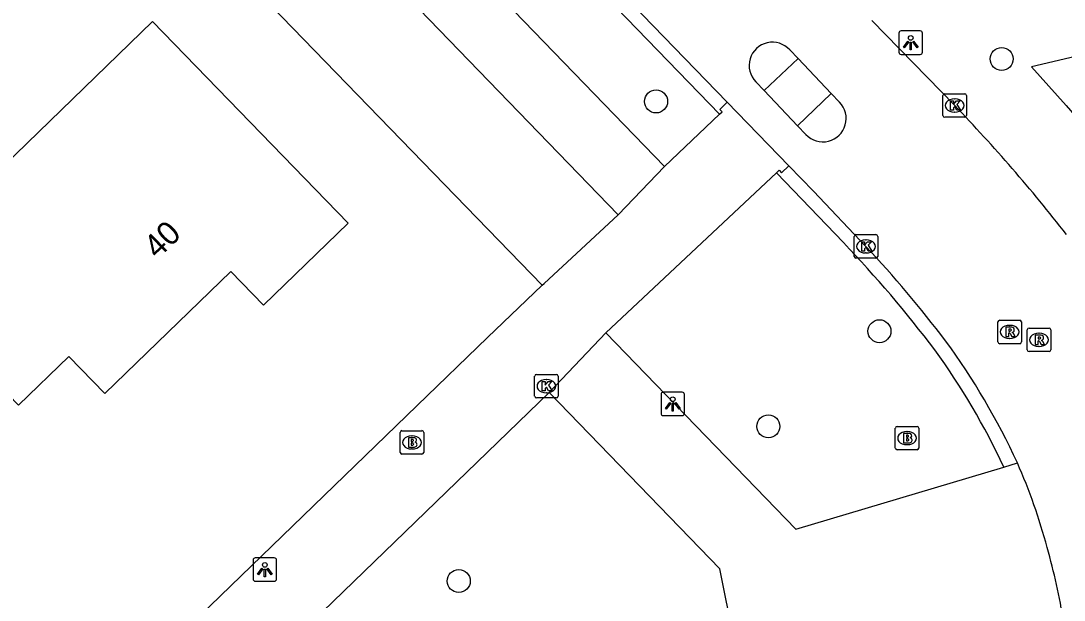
# Model space of a CAD drawing. Extents: x 157663 to 158496, y 379212 to 380934.
# Drawn here: x 158083.8 to 158128.21, y 380348.23 to 380372.89 of the extents above; entities that cross this region are included whole.
import ezdxf

# ---------------------------------------------------------------- set-up
doc = ezdxf.new("R2010")
doc.units = 0
for name, color, linetype in [('IMGEO_Boom', 7, 'Continuous'), ('IMGEO_Brandkraan', 7, 'Continuous'), ('IMGEO_Groenvoorziening', 7, 'Continuous'), ('IMGEO_Kolk', 7, 'Continuous'), ('IMGEO_Lichtpunt', 7, 'Continuous'), ('IMGEO_Pand', 7, 'Continuous'), ('IMGEO_Pand_nummerreeks', 7, 'Continuous'), ('IMGEO_Rijbaan_lokaal_open', 7, 'Continuous'), ('IMGEO_Rioolput', 7, 'Continuous'), ('IMGEO_Voetpad_open', 7, 'Continuous')]:
    doc.layers.add(name, color=color, linetype=linetype)

msp = doc.modelspace()

# ---------------------------------------------------------------- linework, layer by layer
at = {"layer": 'IMGEO_Boom'}
for centre in [(158125.552, 380371.264), (158110.84, 380369.456), (158120.35, 380359.676), (158115.62, 380355.624), (158102.44, 380349.041)]:
    msp.add_circle(centre, 0.489, dxfattribs=at)
at = {"layer": 'IMGEO_Brandkraan'}
for p, q in [((158121.025, 380354.7), (158121.025, 380355.552)), ((158121.1, 380355.626), (158121.952, 380355.626)), ((158122.026, 380355.552), (158122.026, 380354.7)), ((158099.945, 380354.516), (158099.945, 380355.368)), ((158100.02, 380355.442), (158100.872, 380355.442)), ((158100.433, 380355.222), (158100.458, 380355.222)), ((158100.946, 380355.368), (158100.946, 380354.516)), ((158121.513, 380355.406), (158121.538, 380355.406)), ((158100.456, 380354.662), (158100.431, 380354.662)), ((158121.952, 380354.626), (158121.1, 380354.626)), ((158121.536, 380354.846), (158121.511, 380354.846)), ((158100.872, 380354.442), (158100.02, 380354.442))]:
    msp.add_line(p, q, dxfattribs=at)
for points in [[(158121.025, 380354.7), (158121.025, 380355.552)], [(158121.1, 380355.626), (158121.952, 380355.626)], [(158122.026, 380355.552), (158122.026, 380354.7)], [(158099.945, 380354.516), (158099.945, 380355.368)], [(158100.02, 380355.442), (158100.872, 380355.442)], [(158100.293, 380355.142), (158100.293, 380354.742), (158100.506, 380354.742)], [(158100.524, 380355.142), (158100.293, 380355.142)], [(158100.472, 380355.061), (158100.418, 380355.061), (158100.418, 380354.985)], [(158100.946, 380355.368), (158100.946, 380354.516)], [(158121.373, 380355.326), (158121.373, 380354.926), (158121.586, 380354.926)], [(158121.604, 380355.326), (158121.373, 380355.326)], [(158121.552, 380355.245), (158121.498, 380355.245), (158121.498, 380355.169)], [(158121.498, 380355.169), (158121.551, 380355.169)], [(158121.56, 380355.093), (158121.498, 380355.093), (158121.498, 380355.012)], [(158100.418, 380354.985), (158100.471, 380354.985)], [(158100.48, 380354.909), (158100.418, 380354.909), (158100.418, 380354.828)], [(158100.418, 380354.828), (158100.48, 380354.828)], [(158121.952, 380354.626), (158121.1, 380354.626)], [(158121.498, 380355.012), (158121.56, 380355.012)], [(158100.872, 380354.442), (158100.02, 380354.442)]]:
    msp.add_lwpolyline(points, dxfattribs=at)
for centre, radius, start, end in [((158121.102, 380355.55), 0.0765, 91.552, 178.448), ((158121.102, 380355.55), 0.0765, 91.552, 178.448), ((158121.95, 380355.55), 0.0765, 1.552, 88.448), ((158121.95, 380355.55), 0.0765, 1.552, 88.448), ((158100.022, 380355.366), 0.0765, 91.552, 178.448), ((158100.022, 380355.366), 0.0765, 91.552, 178.448), ((158100.473, 380355.023), 0.0379, 267.8285, 90.9355), ((158100.528, 380354.997), 0.145, 59.4692, 91.5367), ((158100.553, 380355.044), 0.0922, 285.5137, 58.1501), ((158100.87, 380355.366), 0.0765, 1.552, 88.448), ((158100.87, 380355.366), 0.0765, 1.552, 88.448), ((158121.553, 380355.207), 0.0379, 267.8285, 90.9355), ((158121.561, 380355.052), 0.0404, 269.8759, 90.5077), ((158121.608, 380355.181), 0.145, 59.4692, 91.5367), ((158121.633, 380355.228), 0.0922, 285.5137, 58.1501), ((158121.638, 380355.036), 0.105, 301.3115, 78.989), ((158100.481, 380354.868), 0.0404, 269.8759, 90.5077), ((158100.512, 380354.993), 0.251, 268.6676, 293.5347), ((158100.558, 380354.852), 0.105, 301.3115, 78.989), ((158121.102, 380354.702), 0.0765, 181.552, 268.448), ((158121.102, 380354.702), 0.0765, 181.552, 268.448), ((158121.592, 380355.177), 0.251, 268.6676, 293.5347), ((158121.95, 380354.702), 0.0765, 271.552, 358.448), ((158121.95, 380354.702), 0.0765, 271.552, 358.448), ((158100.022, 380354.518), 0.0765, 181.552, 268.448), ((158100.022, 380354.518), 0.0765, 181.552, 268.448), ((158100.87, 380354.518), 0.0765, 271.552, 358.448), ((158100.87, 380354.518), 0.0765, 271.552, 358.448)]:
    msp.add_arc(centre, radius, start, end, dxfattribs=at)
for centre, major_axis, ratio, start_param, end_param in [((158100.432, 380354.942), (-0.387, 0.002), 0.722429, 4.712389, 7.853982), ((158100.457, 380354.942), (-0.39, 0.002), 0.717154, 1.570796, 4.712389), ((158121.512, 380355.126), (-0.387, 0.002), 0.722429, 4.712389, 7.853982), ((158121.537, 380355.126), (-0.39, 0.002), 0.717154, 1.570796, 4.712389)]:
    msp.add_ellipse(centre, major_axis=major_axis, ratio=ratio, start_param=start_param, end_param=end_param, dxfattribs=at)
at = {"layer": 'IMGEO_Groenvoorziening'}
msp.add_lwpolyline([(158105.995, 380361.632), (158075.944, 380392.592), (158075.753, 380392.408), (158075.676, 380392.485), (158052.218, 380370.37), (158052.442, 380369.146), (158059.5, 380330.252), (158063.82, 380331.088)], dxfattribs=at)
at = {"layer": 'IMGEO_Kolk'}
for p, q in [((158123.052, 380368.855), (158123.052, 380369.707)), ((158123.127, 380369.781), (158123.979, 380369.781)), ((158124.053, 380369.707), (158124.053, 380368.855)), ((158123.54, 380369.561), (158123.565, 380369.561)), ((158123.563, 380369.001), (158123.538, 380369.001)), ((158123.979, 380368.781), (158123.127, 380368.781)), ((158119.273, 380362.859), (158119.273, 380363.711)), ((158119.348, 380363.785), (158120.2, 380363.785)), ((158119.761, 380363.565), (158119.786, 380363.565)), ((158120.274, 380363.711), (158120.274, 380362.859)), ((158120.2, 380362.785), (158119.348, 380362.785)), ((158119.784, 380363.005), (158119.759, 380363.005)), ((158105.671, 380356.908), (158105.671, 380357.76)), ((158105.746, 380357.834), (158106.598, 380357.834)), ((158106.672, 380357.76), (158106.672, 380356.908)), ((158106.159, 380357.614), (158106.184, 380357.614)), ((158106.598, 380356.834), (158105.746, 380356.834)), ((158106.182, 380357.054), (158106.157, 380357.054))]:
    msp.add_line(p, q, dxfattribs=at)
for points in [[(158123.052, 380368.855), (158123.052, 380369.707)], [(158123.127, 380369.781), (158123.979, 380369.781)], [(158124.053, 380369.707), (158124.053, 380368.855)], [(158123.373, 380369.481), (158123.496, 380369.481), (158123.496, 380369.33), (158123.626, 380369.481), (158123.79, 380369.481), (158123.644, 380369.33), (158123.797, 380369.081), (158123.645, 380369.081), (158123.56, 380369.245), (158123.496, 380369.178), (158123.496, 380369.081), (158123.373, 380369.081), (158123.373, 380369.481)], [(158123.979, 380368.781), (158123.127, 380368.781)], [(158119.273, 380362.859), (158119.273, 380363.711)], [(158119.348, 380363.785), (158120.2, 380363.785)], [(158119.594, 380363.485), (158119.717, 380363.485), (158119.717, 380363.334), (158119.847, 380363.485), (158120.011, 380363.485), (158119.865, 380363.334), (158120.018, 380363.085), (158119.866, 380363.085), (158119.781, 380363.249), (158119.717, 380363.182), (158119.717, 380363.085), (158119.594, 380363.085), (158119.594, 380363.485)], [(158120.274, 380363.711), (158120.274, 380362.859)], [(158120.2, 380362.785), (158119.348, 380362.785)], [(158105.671, 380356.908), (158105.671, 380357.76)], [(158105.746, 380357.834), (158106.598, 380357.834)], [(158106.672, 380357.76), (158106.672, 380356.908)], [(158105.992, 380357.534), (158106.115, 380357.534), (158106.115, 380357.383), (158106.245, 380357.534), (158106.409, 380357.534), (158106.263, 380357.383), (158106.416, 380357.134), (158106.264, 380357.134), (158106.179, 380357.298), (158106.115, 380357.231), (158106.115, 380357.134), (158105.992, 380357.134), (158105.992, 380357.534)], [(158106.598, 380356.834), (158105.746, 380356.834)]]:
    msp.add_lwpolyline(points, dxfattribs=at)
for centre, start, end in [((158123.129, 380369.705), 91.552, 178.448), ((158123.129, 380369.705), 91.552, 178.448), ((158123.977, 380369.705), 1.552, 88.448), ((158123.977, 380369.705), 1.552, 88.448), ((158123.129, 380368.857), 181.552, 268.448), ((158123.129, 380368.857), 181.552, 268.448), ((158123.977, 380368.857), 271.552, 358.448), ((158123.977, 380368.857), 271.552, 358.448), ((158119.35, 380363.709), 91.552, 178.448), ((158119.35, 380363.709), 91.552, 178.448), ((158120.198, 380363.709), 1.552, 88.448), ((158120.198, 380363.709), 1.552, 88.448), ((158119.35, 380362.861), 181.552, 268.448), ((158119.35, 380362.861), 181.552, 268.448), ((158120.198, 380362.861), 271.552, 358.448), ((158120.198, 380362.861), 271.552, 358.448), ((158105.748, 380357.758), 91.552, 178.448), ((158105.748, 380357.758), 91.552, 178.448), ((158106.596, 380357.758), 1.552, 88.448), ((158106.596, 380357.758), 1.552, 88.448), ((158105.748, 380356.91), 181.552, 268.448), ((158105.748, 380356.91), 181.552, 268.448), ((158106.596, 380356.91), 271.552, 358.448), ((158106.596, 380356.91), 271.552, 358.448)]:
    msp.add_arc(centre, 0.0765, start, end, dxfattribs=at)
for centre, major_axis, ratio, start_param, end_param in [((158123.539, 380369.281), (-0.387, 0.002), 0.722429, 4.712389, 7.853982), ((158123.564, 380369.281), (-0.39, 0.002), 0.717154, 1.570796, 4.712389), ((158119.76, 380363.285), (-0.387, 0.002), 0.722429, 4.712389, 7.853982), ((158119.785, 380363.285), (-0.39, 0.002), 0.717154, 1.570796, 4.712389), ((158106.158, 380357.334), (-0.387, 0.002), 0.722429, 4.712389, 7.853982), ((158106.183, 380357.334), (-0.39, 0.002), 0.717154, 1.570796, 4.712389)]:
    msp.add_ellipse(centre, major_axis=major_axis, ratio=ratio, start_param=start_param, end_param=end_param, dxfattribs=at)
at = {"layer": 'IMGEO_Lichtpunt'}
for p, q in [((158121.18, 380372.361), (158121.18, 380371.554)), ((158121.18, 380372.361), (158121.18, 380371.554)), ((158122.082, 380372.456), (158121.274, 380372.456)), ((158122.082, 380372.456), (158121.274, 380372.456)), ((158122.176, 380371.554), (158122.176, 380372.361)), ((158122.176, 380371.554), (158122.176, 380372.361)), ((158121.274, 380371.46), (158122.082, 380371.46)), ((158121.274, 380371.46), (158122.082, 380371.46)), ((158111.05, 380356.983), (158111.05, 380356.176)), ((158111.05, 380356.983), (158111.05, 380356.176)), ((158111.952, 380357.078), (158111.144, 380357.078)), ((158111.952, 380357.078), (158111.144, 380357.078)), ((158112.046, 380356.176), (158112.046, 380356.983)), ((158112.046, 380356.176), (158112.046, 380356.983)), ((158111.144, 380356.082), (158111.952, 380356.082)), ((158111.144, 380356.082), (158111.952, 380356.082)), ((158093.685, 380349.932), (158093.685, 380349.125)), ((158093.685, 380349.932), (158093.685, 380349.125)), ((158094.587, 380350.027), (158093.779, 380350.027)), ((158094.587, 380350.027), (158093.779, 380350.027)), ((158094.681, 380349.125), (158094.681, 380349.932)), ((158094.681, 380349.125), (158094.681, 380349.932)), ((158093.779, 380349.031), (158094.587, 380349.031)), ((158093.779, 380349.031), (158094.587, 380349.031))]:
    msp.add_line(p, q, dxfattribs=at)
for points in [[(158121.554, 380372.025), (158121.593, 380371.997), (158121.405, 380371.735), (158121.367, 380371.762), (158121.554, 380372.025)], [(158121.656, 380371.977), (158121.703, 380371.977), (158121.703, 380371.655), (158121.656, 380371.655), (158121.656, 380371.977)], [(158121.766, 380371.997), (158121.804, 380372.024), (158121.991, 380371.762), (158121.952, 380371.734), (158121.766, 380371.997)], [(158111.424, 380356.647), (158111.463, 380356.619), (158111.275, 380356.357), (158111.237, 380356.384), (158111.424, 380356.647)], [(158111.526, 380356.599), (158111.573, 380356.599), (158111.573, 380356.277), (158111.526, 380356.277), (158111.526, 380356.599)], [(158111.636, 380356.619), (158111.674, 380356.646), (158111.861, 380356.384), (158111.822, 380356.356), (158111.636, 380356.619)], [(158094.059, 380349.596), (158094.098, 380349.568), (158093.91, 380349.306), (158093.872, 380349.333), (158094.059, 380349.596)], [(158094.161, 380349.548), (158094.208, 380349.548), (158094.208, 380349.226), (158094.161, 380349.226), (158094.161, 380349.548)], [(158094.271, 380349.568), (158094.309, 380349.595), (158094.496, 380349.333), (158094.457, 380349.305), (158094.271, 380349.568)]]:
    msp.add_lwpolyline(points, dxfattribs=at)
for centre in [(158121.679, 380372.159), (158111.549, 380356.781), (158094.184, 380349.73)]:
    msp.add_circle(centre, 0.0994, dxfattribs=at)
for centre, start, end in [((158121.274, 380372.361), 90, 180), ((158121.274, 380372.361), 90, 180), ((158122.082, 380372.361), 0, 90), ((158122.082, 380372.361), 0, 90), ((158121.274, 380371.554), 180, 270), ((158121.274, 380371.554), 180, 270), ((158122.082, 380371.554), 270, 0), ((158122.082, 380371.554), 270, 360), ((158111.144, 380356.983), 90, 180), ((158111.144, 380356.983), 90, 180), ((158111.952, 380356.983), 0, 90), ((158111.952, 380356.983), 0, 90), ((158111.144, 380356.176), 180, 270), ((158111.144, 380356.176), 180, 270), ((158111.952, 380356.176), 270, 0), ((158111.952, 380356.176), 270, 360), ((158093.779, 380349.932), 90, 180), ((158093.779, 380349.932), 90, 180), ((158094.587, 380349.932), 0, 90), ((158094.587, 380349.932), 0, 90), ((158093.779, 380349.125), 180, 270), ((158093.779, 380349.125), 180, 270), ((158094.587, 380349.125), 270, 0), ((158094.587, 380349.125), 270, 360)]:
    msp.add_arc(centre, 0.0946, start, end, dxfattribs=at)
at = {"layer": 'IMGEO_Pand'}
msp.add_lwpolyline([(158087.367, 380357.019), (158085.835, 380358.598), (158083.703, 380356.53), (158076.024, 380364.445), (158075.857, 380364.617), (158078.684, 380367.359), (158081.127, 380364.84), (158089.399, 380372.864), (158097.735, 380364.271), (158094.134, 380360.778), (158092.731, 380362.224), (158087.367, 380357.019)], dxfattribs=at)
at = {"layer": 'IMGEO_Rijbaan_lokaal_open'}
for points in [[(158113.871, 380369.425), (158099.931, 380383.806)], [(158120.025, 380372.906), (158123.553, 380369.281)], [(158116.894, 380371.29), (158116.528, 380371.649)], [(158116.894, 380371.29), (158118.291, 380369.799)], [(158115.083, 380370.294), (158115.44, 380369.92)], [(158116.857, 380368.42), (158115.44, 380369.92)], [(158118.643, 380369.424), (158118.291, 380369.799)], [(158116.496, 380366.721), (158113.871, 380369.425)], [(158116.857, 380368.42), (158117.221, 380368.05)], [(158116.496, 380366.721), (158117.545, 380365.64), (158119.774, 380363.285)]]:
    msp.add_lwpolyline(points, dxfattribs=at)
for centre, radius, start, end in [((158115.792, 380370.986), 0.991, 42.0256, 224.2924), ((158117.944, 380368.725), 0.989, 223.0415, 44.9914), ((158070.396, 380318.319), 73.64, 38.13735, 43.79233), ((158083.404, 380329.178), 49.86, 37.1231, 43.1613), ((158099.018, 380341.558), 29.943, 24.7004, 36.2663), ((158104.288, 380344.344), 23.993, 14.7771, 23.9133), ((158103.173, 380343.419), 25.314, 8.7999, 16.1583)]:
    msp.add_arc(centre, radius, start, end, dxfattribs=at)
at = {"layer": 'IMGEO_Rioolput'}
for p, q in [((158125.393, 380359.219), (158125.393, 380360.071)), ((158125.468, 380360.145), (158126.32, 380360.145)), ((158125.881, 380359.925), (158125.906, 380359.925)), ((158126.394, 380360.071), (158126.394, 380359.219)), ((158126.641, 380358.882), (158126.641, 380359.734)), ((158126.716, 380359.808), (158127.568, 380359.808)), ((158127.129, 380359.588), (158127.154, 380359.588)), ((158127.642, 380359.734), (158127.642, 380358.882)), ((158126.32, 380359.145), (158125.468, 380359.145)), ((158125.904, 380359.365), (158125.879, 380359.365)), ((158127.152, 380359.028), (158127.127, 380359.028)), ((158127.568, 380358.808), (158126.716, 380358.808))]:
    msp.add_line(p, q, dxfattribs=at)
for points in [[(158125.393, 380359.219), (158125.393, 380360.071)], [(158125.468, 380360.145), (158126.32, 380360.145)], [(158126.394, 380360.071), (158126.394, 380359.219)], [(158125.982, 380359.843), (158125.73, 380359.845), (158125.73, 380359.445)], [(158125.73, 380359.445), (158125.854, 380359.445), (158125.854, 380359.607), (158125.865, 380359.607)], [(158125.908, 380359.764), (158125.854, 380359.764), (158125.854, 380359.683)], [(158125.854, 380359.683), (158125.906, 380359.683)], [(158125.912, 380359.578), (158125.983, 380359.445), (158126.123, 380359.445), (158126.058, 380359.571)], [(158126.641, 380358.882), (158126.641, 380359.734)], [(158126.716, 380359.808), (158127.568, 380359.808)], [(158127.23, 380359.506), (158126.978, 380359.508), (158126.978, 380359.108)], [(158127.642, 380359.734), (158127.642, 380358.882)], [(158126.32, 380359.145), (158125.468, 380359.145)], [(158126.978, 380359.108), (158127.102, 380359.108), (158127.102, 380359.27), (158127.113, 380359.27)], [(158127.156, 380359.427), (158127.102, 380359.427), (158127.102, 380359.346)], [(158127.102, 380359.346), (158127.154, 380359.346)], [(158127.16, 380359.241), (158127.231, 380359.108), (158127.371, 380359.108), (158127.306, 380359.234)], [(158127.568, 380358.808), (158126.716, 380358.808)]]:
    msp.add_lwpolyline(points, dxfattribs=at)
for centre, radius, start, end in [((158125.47, 380360.069), 0.0765, 91.552, 178.448), ((158125.47, 380360.069), 0.0765, 91.552, 178.448), ((158126.318, 380360.069), 0.0765, 1.552, 88.448), ((158126.318, 380360.069), 0.0765, 1.552, 88.448), ((158125.864, 380359.554), 0.0533, 26.0293, 88.6989), ((158125.89, 380359.872), 0.19, 274.7715, 282.9687), ((158125.914, 380359.668), 0.0964, 77.0061, 93.1865), ((158125.928, 380359.725), 0.0378, 276.6634, 79.6772), ((158125.981, 380359.733), 0.109, 350.3612, 89.416), ((158125.979, 380359.733), 0.112, 277.5842, 350.9817), ((158125.963, 380359.518), 0.108, 29.5134, 73.7905), ((158126.718, 380359.732), 0.0765, 91.552, 178.448), ((158126.718, 380359.732), 0.0765, 91.552, 178.448), ((158127.229, 380359.396), 0.109, 350.3612, 89.416), ((158127.566, 380359.732), 0.0765, 1.552, 88.448), ((158127.566, 380359.732), 0.0765, 1.552, 88.448), ((158125.47, 380359.221), 0.0765, 181.552, 268.448), ((158125.47, 380359.221), 0.0765, 181.552, 268.448), ((158126.318, 380359.221), 0.0765, 271.552, 358.448), ((158126.318, 380359.221), 0.0765, 271.552, 358.448), ((158127.112, 380359.217), 0.0533, 26.0293, 88.6989), ((158127.138, 380359.535), 0.19, 274.7715, 282.9687), ((158127.162, 380359.331), 0.0964, 77.0061, 93.1865), ((158127.176, 380359.388), 0.0378, 276.6634, 79.6772), ((158127.227, 380359.396), 0.112, 277.5842, 350.9817), ((158127.211, 380359.181), 0.108, 29.5134, 73.7905), ((158126.718, 380358.884), 0.0765, 181.552, 268.448), ((158126.718, 380358.884), 0.0765, 181.552, 268.448), ((158127.566, 380358.884), 0.0765, 271.552, 358.448), ((158127.566, 380358.884), 0.0765, 271.552, 358.448)]:
    msp.add_arc(centre, radius, start, end, dxfattribs=at)
for centre, major_axis, ratio, start_param, end_param in [((158125.88, 380359.645), (-0.387, 0.002), 0.722429, 4.712389, 7.853982), ((158125.905, 380359.645), (-0.39, 0.002), 0.717154, 1.570796, 4.712389), ((158127.128, 380359.308), (-0.387, 0.002), 0.722429, 4.712389, 7.853982), ((158127.153, 380359.308), (-0.39, 0.002), 0.717154, 1.570796, 4.712389)]:
    msp.add_ellipse(centre, major_axis=major_axis, ratio=ratio, start_param=start_param, end_param=end_param, dxfattribs=at)
at = {"layer": 'IMGEO_Voetpad_open'}
for points in [[(158111.192, 380366.685), (158093.226, 380385.279), (158095.545, 380387.499), (158113.544, 380368.914)], [(158109.224, 380364.626), (158090.592, 380383.892), (158090.472, 380384.897)], [(158143.242, 380374.803), (158126.816, 380370.925), (158127.564, 380370.111), (158128.3, 380369.287), (158129.024, 380368.452), (158129.736, 380367.607), (158130.436, 380366.751), (158131.123, 380365.886), (158133.759, 380362.09), (158145.562, 380364.862)], [(158115.44, 380369.92), (158116.894, 380371.29)], [(158118.291, 380369.799), (158116.857, 380368.42)], [(158113.544, 380368.914), (158113.647, 380369.012), (158113.548, 380369.117), (158113.871, 380369.425)], [(158113.544, 380368.914), (158111.192, 380366.685)], [(158109.224, 380364.626), (158111.192, 380366.685)], [(158115.965, 380366.418), (158116.081, 380366.527), (158116.182, 380366.423), (158116.496, 380366.721)], [(158108.705, 380359.612), (158115.965, 380366.418)], [(158118.813, 380363.445), (158115.965, 380366.418)], [(158105.995, 380361.632), (158106.073, 380361.706), (158109.224, 380364.626)], [(158115.735, 380338.668), (158104.594, 380336.436), (158105.235, 380333.559), (158087.167, 380330.005), (158084.961, 380341.306), (158091.847, 380347.972), (158100.664, 380356.509), (158103.667, 380359.403), (158105.995, 380361.632)], [(158106.293, 380357.072), (158108.705, 380359.612)], [(158108.705, 380359.612), (158116.783, 380351.251), (158125.643, 380353.888)], [(158115.35, 380340.589), (158100.719, 380337.733), (158101.038, 380336.301), (158089.931, 380334.116), (158088.76, 380340.112), (158106.293, 380357.072)], [(158115.35, 380340.589), (158113.553, 380349.557), (158106.293, 380357.072)], [(158125.643, 380353.888), (158126.221, 380354.07)]]:
    msp.add_lwpolyline(points, dxfattribs=at)
for centre, radius, start, end in [((158082.131, 380328.247), 50.838, 37.048, 43.8171), ((158098.681, 380341.371), 29.726, 24.9028, 36.0775)]:
    msp.add_arc(centre, radius, start, end, dxfattribs=at)

# ---------------------------------------------------------------- texts
at = {"layer": 'IMGEO_Pand_nummerreeks'}
msp.add_text('40', height=1, rotation=44.1407, dxfattribs=at).set_placement((158089.616, 380362.712))

doc.saveas('drawing.dxf')
